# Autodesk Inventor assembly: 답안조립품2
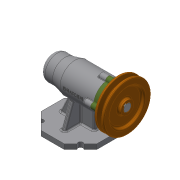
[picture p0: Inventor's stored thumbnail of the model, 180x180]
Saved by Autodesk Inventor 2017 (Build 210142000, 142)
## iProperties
Created: 2019-12
Part Number: 답안조립품2
Document SubType Name: Assembly
Designer: 5-14-le-1
Author: 5-14-le-1
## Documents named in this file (12)
- C:\Users\5-14-le-1\Desktop\491204V1006\답안조립품.iam
- C:\Users\5-14-le-1\Desktop\491204V1006\본체.ipt
- C:\Users\5-14-le-1\Desktop\491204V1006\베어링 6004.ipt
- C:\Users\5-14-le-1\Desktop\491204V1006\베어링 51202.ipt
- C:\Users\5-14-le-1\Desktop\491204V1006\볼트 M4.ipt
- C:\Users\5-14-le-1\Desktop\491204V1006\어댑터슬리브.ipt
- C:\Users\5-14-le-1\Desktop\491204V1006\오일 실.ipt
- C:\Users\5-14-le-1\Desktop\491204V1006\축.ipt
- C:\Users\5-14-le-1\Desktop\491204V1006\커버.ipt
- C:\Users\5-14-le-1\Desktop\491204V1006\키 5 x 5 x 16.ipt
- C:\Users\5-14-le-1\Desktop\491204V1006\V벨트풀리.ipt
- C:\Users\5-14-le-1\Desktop\491204V1006\멈춤나사 M3.ipt
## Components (1 placed, 1 different names)
1. V벨트풀리:1
